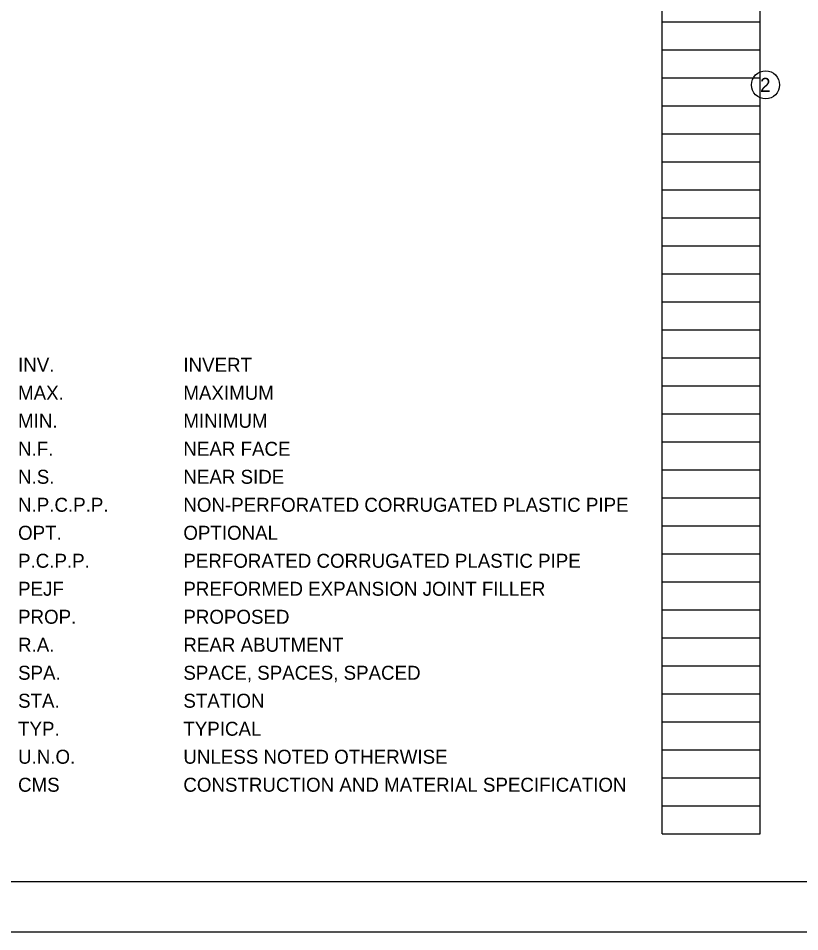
# Model space of a CAD drawing. Extents: x 0 to 34, y 0 to 22.
# Drawn here: x 17.24 to 25.06, y 0 to 9.14 of the extents above; entities that cross this region are included whole.
import ezdxf

# ---------------------------------------------------------------- set-up
doc = ezdxf.new("R2010")
doc.units = 0
for name, color, linetype in [('BR_P_Gen_Text', 7, 'Continuous'), ('SH_Border', 7, 'Continuous'), ('SH_Cut_Line', 7, 'Continuous'), ('SH_Data', 7, 'Continuous')]:
    doc.layers.add(name, color=color, linetype=linetype)

msp = doc.modelspace()

# ---------------------------------------------------------------- linework, layer by layer
at = {"layer": 'BR_P_Gen_Text'}
msp.add_circle((24.715, 8.47), 0.14, dxfattribs=at)
at = {"layer": 'SH_Border'}
msp.add_lwpolyline([(1.5, 21.5), (33.5, 21.5), (33.5, 0.5), (1.5, 0.5)], close=True, dxfattribs=at)
at = {"layer": 'SH_Cut_Line'}
msp.add_lwpolyline([(0, 0), (34, 0), (34, 22), (0, 22)], close=True, dxfattribs=at)
at = {"layer": 'SH_Data'}
for p, q in [((23.68, 0.98), (23.68, 21.14)), ((24.66, 0.98), (24.66, 21.14)), ((23.68, 9.1), (24.66, 9.1)), ((23.68, 8.82), (24.66, 8.82)), ((23.68, 8.54), (24.66, 8.54)), ((23.68, 8.26), (24.66, 8.26)), ((23.68, 7.98), (24.66, 7.98)), ((23.68, 7.7), (24.66, 7.7)), ((23.68, 7.42), (24.66, 7.42)), ((23.68, 7.14), (24.66, 7.14)), ((23.68, 6.86), (24.66, 6.86)), ((23.68, 6.58), (24.66, 6.58)), ((23.68, 6.3), (24.66, 6.3)), ((23.68, 6.02), (24.66, 6.02)), ((23.68, 5.74), (24.66, 5.74)), ((23.68, 5.46), (24.66, 5.46)), ((23.68, 5.18), (24.66, 5.18)), ((23.68, 4.9), (24.66, 4.9)), ((23.68, 4.62), (24.66, 4.62)), ((23.68, 4.34), (24.66, 4.34)), ((23.68, 4.06), (24.66, 4.06)), ((23.68, 3.78), (24.66, 3.78)), ((23.68, 3.5), (24.66, 3.5)), ((23.68, 3.22), (24.66, 3.22)), ((23.68, 2.94), (24.66, 2.94)), ((23.68, 2.66), (24.66, 2.66)), ((23.68, 2.38), (24.66, 2.38)), ((23.68, 2.1), (24.66, 2.1)), ((23.68, 1.82), (24.66, 1.82)), ((23.68, 1.54), (24.66, 1.54)), ((23.68, 1.26), (24.66, 1.26)), ((23.68, 0.98), (24.66, 0.98))]:
    msp.add_line(p, q, dxfattribs=at)

# ---------------------------------------------------------------- texts
at = {"layer": 'BR_P_Gen_Text'}
for s, p in [('2', (24.66, 8.4)), ('INV.', (17.24, 5.6)), ('INVERT', (18.893, 5.6)), ('MAX.       ', (17.24, 5.32)), ('MAXIMUM', (18.893, 5.32)), ('MIN.        ', (17.24, 5.04)), ('MINIMUM', (18.893, 5.04)), ('N.F.        ', (17.24, 4.76)), ('NEAR FACE', (18.893, 4.76)), ('N.S.            ', (17.24, 4.48)), ('NEAR SIDE', (18.893, 4.48)), ('N.P.C.P.P.  ', (17.24, 4.2)), ('NON-PERFORATED CORRUGATED PLASTIC PIPE', (18.893, 4.2)), ('OPT.            ', (17.24, 3.92)), ('OPTIONAL', (18.893, 3.92)), ('P.C.P.P.       ', (17.24, 3.64)), ('PERFORATED CORRUGATED PLASTIC PIPE', (18.893, 3.64)), ('PEJF            ', (17.24, 3.36)), ('PREFORMED EXPANSION JOINT FILLER', (18.893, 3.36)), ('PROP.          ', (17.24, 3.08)), ('PROPOSED', (18.893, 3.08)), ('R.A.              ', (17.24, 2.8)), ('REAR ABUTMENT', (18.893, 2.8)), ('SPA.            ', (17.24, 2.52)), ('SPACE, SPACES, SPACED', (18.893, 2.52)), ('STA.           ', (17.24, 2.24)), ('STATION', (18.893, 2.24)), ('TYPICAL', (18.893, 1.96)), ('TYP.            ', (17.24, 1.96)), ('U.N.O.          ', (17.24, 1.68)), ('UNLESS NOTED OTHERWISE', (18.893, 1.68)), ('CMS             ', (17.24, 1.4)), ('CONSTRUCTION AND MATERIAL SPECIFICATION', (18.893, 1.4))]:
    msp.add_text(s, height=0.14, dxfattribs=at).set_placement(p)

doc.saveas('drawing.dxf')
